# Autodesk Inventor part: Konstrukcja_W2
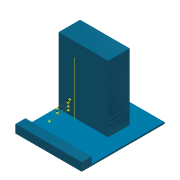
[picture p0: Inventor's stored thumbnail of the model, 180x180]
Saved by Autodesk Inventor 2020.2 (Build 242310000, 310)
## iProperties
Created: 2014-09
Part Number: Konstrukcja_W2
Material: Ogólny
Document SubType Name: Modeling
Designer: F.Stasiak
Density: 1 g/cm^3
Appearance: Ciemnobłękitna
Catalog Web Link: www.expertbooks.pl
Manager: www.cadconsulting.pl
Company: Fabian Stasiak CAD Consulting
Author: F.Stasiak
Subject: Zbiór ćwiczeń. Autodesk Inventor 2020. Kurs Professional
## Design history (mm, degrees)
sketch "Szkic1"
  geometry: L1 (-100, 125)-(100, 125); L2 (100, 125)-(100, -125); L3 (100, -125)-(-100, -125); L4 (-100, -125)-(-100, 125); L5 (-100, 125)-(100, -125); L6 (100, 125)-(-100, -125); 1 further point
  constraints: 12 end point, 2 midpoint, 2 parallel, 1 horizontal, 1 perpendicular
  dimensions: "d0" = 200 distance of L2.end L3.end; "d1" = 250 distance of L1.end L2.end
extrude "Wyciągnięcie proste1" new body sketch "Szkic1" distance "d2" = 5; taper "d3" = 0 deg
sketch "Szkic2"
  geometry: L1 (100, 125)-(-100, 125) reference; L2 (-100, 125)-(-100, -125) reference; L3 (-100, -125)-(100, -125) reference; L4 (100, -125)-(100, 125) reference; L5 (100, -125)-(-100, -125); L6 (-100, -125)-(-100, -95); L7 (-100, -95)-(100, -95); L8 (100, -95)-(100, -125); L9 (-100, 125)-(-100, -125) reference; 1 further point
  constraints: 8 end point, 2 parallel, 1 collinear, 1 horizontal, 1 perpendicular
  dimensions: "d5" = 30 distance of L5.end L6.end
extrude "Wyciągnięcie proste2" join sketch "Szkic2" distance "d6" = 20; taper "d7" = 0 deg
sketch "Szkic3"
  geometry: L1 (55, 0)-(-95, 0); L2 (-95, 0)-(-95, 65); L3 (-95, 65)-(55, 65); L4 (55, 65)-(55, 0); L5 (-100, -125)-(-100, 125) reference; 1 further point
  constraints: 8 end point, 2 parallel, 1 horizontal, 1 perpendicular, 1 point on line
  dimensions: "d8" = 150 distance of L2.end L3.end; "d9" = 65 distance of L1.end L2.end; "d10" = 5 distance between parallel lines of L5 L2
extrude "Wyciągnięcie proste3" join sketch "Szkic3" distance "d11" = 200; taper "d12" = 0 deg
node "Płaszczyzna konstrukcyjna1"
sketch "Szkic pomocniczy"
  geometry: L1 (41.417, -21.187)-(41.417, -54.914); L2 (51.417, -54.914)-(51.417, -21.187); L3 (31.417, -21.187)-(31.417, -78.704); L4 (36.417, -21.187)-(56.417, -21.187); L5 (56.417, -21.187)-(56.417, -54.914); L6 (56.417, -54.914)-(36.417, -54.914); L7 (36.417, -54.914)-(36.417, -21.187); A1 r 5 centre (36.417, -21.187) between (41.417, -21.187) and (31.417, -21.187); A2 r 5 centre (46.417, -54.914) between (41.417, -54.914) and (51.417, -54.914); A3 r 5 centre (56.417, -21.187) between (56.833, -16.204) and (51.417, -21.187); 2 further points
  constraints: 14 end point, 6 point on circle, 5 tangent, 3 centre point, 3 parallel, 2 coincident, 2 equal radius, 1 horizontal, 1 midpoint, 1 perpendicular, 1 vertical
node "Punkt konstrukcyjny1"
node "Punkt konstrukcyjny2"
node "Punkt konstrukcyjny3"
node "Punkt konstrukcyjny4"
node "Punkt konstrukcyjny5"
node "Punkt konstrukcyjny6"
node "Punkt konstrukcyjny7"
node "Bryła1"
node "Pętla rzutowana1"
